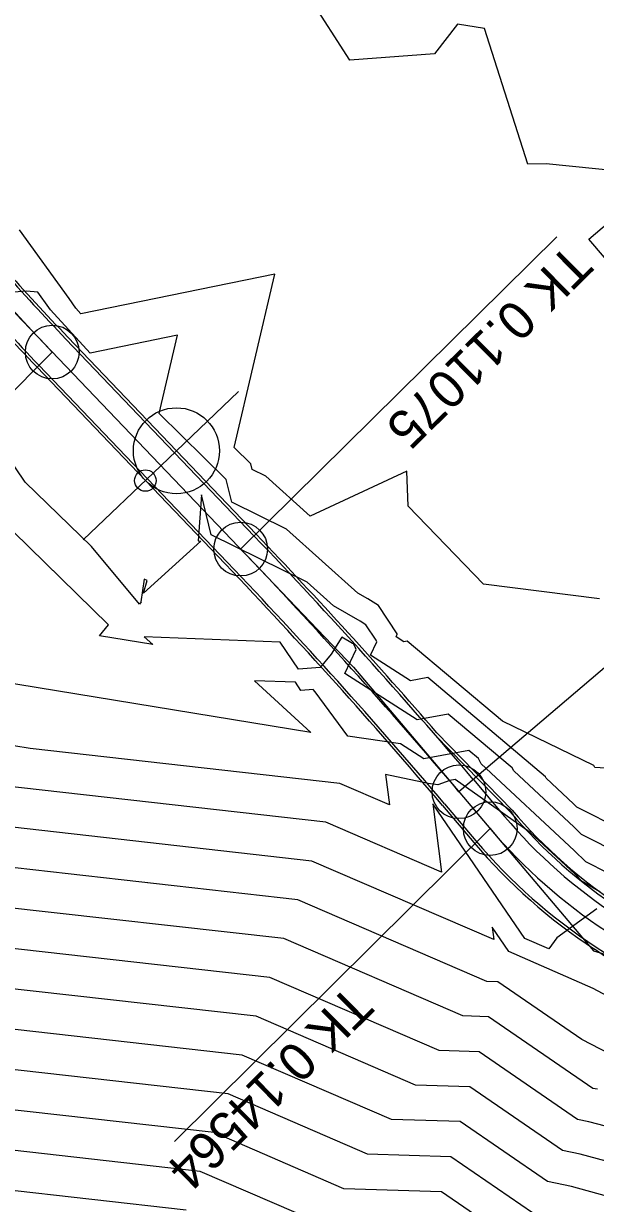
# Model space of a CAD drawing. Extents: x -549394 to -546608, y -1037055 to -1033629.
# Drawn here: x -547053.3 to -547000.1, y -1035904.5 to -1035794.7 of the extents above; entities that cross this region are included whole.
import ezdxf

# ---------------------------------------------------------------- set-up
doc = ezdxf.new("R2010")
doc.units = 0
for name, color, linetype in [('hlavni_vrst', 7, 'Continuous'), ('norm_vrst', 7, 'Continuous'), ('POLYGONY_SITUACE_PO', 7, 'Continuous'), ('u_sirka_7m', 7, 'Continuous'), ('x_navrh_C31', 7, 'Continuous'), ('x_osa_C31', 7, 'Continuous'), ('x_popis_oblouky_C31', 7, 'Continuous'), ('x_popis_pricne_rezy_C31', 7, 'Continuous')]:
    doc.layers.add(name, color=color, linetype=linetype)

msp = doc.modelspace()

# ---------------------------------------------------------------- linework, layer by layer
at = {"layer": 'hlavni_vrst'}
for p, q in [((-547022.93, -1035798.11), (-547032.16, -1035783.69)), ((-547012.88, -1035794.76), (-547015.05, -1035797.51)), ((-547010.39, -1035795.15), (-547012.88, -1035794.76)), ((-547006.35, -1035807.78), (-547010.39, -1035795.15)), ((-547015.05, -1035797.51), (-547022.93, -1035798.11)), ((-547004.64, -1035807.74), (-547006.35, -1035807.78)), ((-546981.44, -1035810.13), (-547004.64, -1035807.74)), ((-547026.55, -1035860.67), (-547059.01, -1035855.36)), ((-547027.98, -1035856), (-547031.79, -1035855.85)), ((-547031.79, -1035855.85), (-547026.55, -1035860.67)), ((-547027.47, -1035856.76), (-547027.98, -1035856)), ((-547026.32, -1035856.66), (-547027.47, -1035856.76)), ((-547026.15, -1035856.88), (-547026.32, -1035856.66)), ((-547023.09, -1035861.02), (-547026.15, -1035856.88)), ((-547018.2, -1035861.72), (-547023.09, -1035861.02)), ((-547016.02, -1035863.11), (-547018.2, -1035861.72)), ((-547011.83, -1035862.34), (-547016.02, -1035863.11)), ((-547010.93, -1035863.1), (-547011.83, -1035862.34)), ((-547010.68, -1035863.58), (-547010.93, -1035863.1)), ((-547002.02, -1035871.66), (-547010.68, -1035863.58)), ((-547000.95, -1035872.71), (-547002.02, -1035871.66)), ((-546998.88, -1035873.76), (-547000.95, -1035872.71)), ((-547029.05, -1035879.86), (-547076.55, -1035874.51)), ((-547012.39, -1035887.05), (-547029.05, -1035879.86)), ((-547010, -1035887.13), (-547012.39, -1035887.05)), ((-547000.3, -1035893.79), (-547010, -1035887.13)), ((-547035.55, -1035897.91), (-547069.97, -1035894.04)), ((-546999.85, -1035893.88), (-547000.3, -1035893.79)), ((-547023.48, -1035903.13), (-547035.55, -1035897.91)), ((-547014.4, -1035903.41), (-547023.48, -1035903.13)), ((-547007.32, -1035908.26), (-547014.4, -1035903.41))]:
    msp.add_line(p, q, dxfattribs=at)
at = {"layer": 'norm_vrst'}
for p, q in [((-547049.05, -1035820.28), (-547053.67, -1035813.88)), ((-547029.89, -1035818), (-547047.95, -1035821.71)), ((-547033.69, -1035834.15), (-547029.89, -1035818)), ((-547053, -1035819.58), (-547058.28, -1035820.05)), ((-547051.96, -1035819.69), (-547053, -1035819.58)), ((-547050.92, -1035821.13), (-547051.96, -1035819.69)), ((-547048.43, -1035821.18), (-547049.05, -1035820.28)), ((-547050.78, -1035821.33), (-547050.92, -1035821.13)), ((-547047.1, -1035825.36), (-547050.78, -1035821.33)), ((-547047.95, -1035821.71), (-547048.43, -1035821.18)), ((-547038.96, -1035823.69), (-547047.1, -1035825.36)), ((-547040.67, -1035830.97), (-547038.96, -1035823.69)), ((-547053.13, -1035837.36), (-547061.62, -1035824.89)), ((-547034.43, -1035837.12), (-547040.67, -1035830.97)), ((-547032.14, -1035835.68), (-547033.69, -1035834.15)), ((-547032.01, -1035836.2), (-547032.14, -1035835.68)), ((-547030.74, -1035836.82), (-547032.01, -1035836.2)), ((-547026.61, -1035840.53), (-547030.74, -1035836.82)), ((-547017.6, -1035836.34), (-547026.61, -1035840.53)), ((-547017.49, -1035839.62), (-547017.6, -1035836.34)), ((-547046.97, -1035843.36), (-547053.13, -1035837.36)), ((-547033.91, -1035839.23), (-547034.43, -1035837.12)), ((-547045.37, -1035850.64), (-547057.84, -1035838.49)), ((-547036.73, -1035838.56), (-547037.02, -1035842.84)), ((-547036.73, -1035838.56), (-547036.73, -1035838.56)), ((-547036.73, -1035838.56), (-547036.73, -1035838.56)), ((-547036.73, -1035838.56), (-547036.73, -1035838.56)), ((-547035.81, -1035842.27), (-547036.73, -1035838.56)), ((-547036.73, -1035838.56), (-547036.73, -1035838.56)), ((-547028.82, -1035841.75), (-547033.91, -1035839.23)), ((-547010.48, -1035846.87), (-547017.49, -1035839.62)), ((-547026.9, -1035846.67), (-547035.81, -1035842.27)), ((-547022.17, -1035847.7), (-547028.82, -1035841.75)), ((-547042.5, -1035848.72), (-547046.97, -1035843.36)), ((-547036.78, -1035842.86), (-547042.12, -1035847.7)), ((-547037.02, -1035842.84), (-547036.78, -1035842.86)), ((-547042.05, -1035846.39), (-547042.36, -1035848.5)), ((-547042.12, -1035847.7), (-547041.78, -1035846.51)), ((-547041.78, -1035846.51), (-547042.05, -1035846.39)), ((-547024.43, -1035848.88), (-547026.9, -1035846.67)), ((-546999.67, -1035848.23), (-547010.48, -1035846.87)), ((-547021.24, -1035848.24), (-547022.17, -1035847.7)), ((-547042.35, -1035848.5), (-547042.5, -1035848.72)), ((-547042.36, -1035848.5), (-547042.35, -1035848.5)), ((-547021.95, -1035850.32), (-547024.43, -1035848.88)), ((-547020.25, -1035848.84), (-547021.24, -1035848.24)), ((-547018.51, -1035851.5), (-547020.25, -1035848.84)), ((-547046.22, -1035851.68), (-547045.37, -1035850.64)), ((-547021.42, -1035850.64), (-547021.95, -1035850.32)), ((-547020.48, -1035852.07), (-547021.42, -1035850.64)), ((-547041.27, -1035852.49), (-547046.22, -1035851.68)), ((-547029.41, -1035852.27), (-547042.07, -1035851.76)), ((-547042.07, -1035851.76), (-547041.27, -1035852.49)), ((-547027.71, -1035854.78), (-547029.41, -1035852.27)), ((-547023.65, -1035851.81), (-547024.65, -1035853.38)), ((-547022.66, -1035852.39), (-547023.65, -1035851.81)), ((-547021, -1035853.48), (-547020.41, -1035852.24)), ((-547020.41, -1035852.24), (-547020.48, -1035852.07)), ((-547018.61, -1035851.77), (-547018.5, -1035851.53)), ((-547017.89, -1035852.23), (-547018.61, -1035851.77)), ((-547018.5, -1035851.53), (-547018.51, -1035851.5)), ((-547017.58, -1035852.17), (-547017.89, -1035852.23)), ((-547008.72, -1035859.63), (-547017.58, -1035852.17)), ((-547024.65, -1035853.38), (-547025.67, -1035854.61)), ((-547023.39, -1035855.18), (-547022.33, -1035852.94)), ((-547022.58, -1035852.43), (-547022.66, -1035852.39)), ((-547022.45, -1035852.64), (-547022.58, -1035852.43)), ((-547022.33, -1035852.94), (-547022.45, -1035852.64)), ((-547017.27, -1035855.86), (-547021, -1035853.48)), ((-547025.67, -1035854.61), (-547027.71, -1035854.78)), ((-547016.64, -1035859.48), (-547023.39, -1035855.18)), ((-547015.67, -1035855.56), (-547017.27, -1035855.86)), ((-547004.7, -1035864.79), (-547015.67, -1035855.56)), ((-547013.75, -1035858.95), (-547016.64, -1035859.48)), ((-547007.82, -1035863.95), (-547013.75, -1035858.95)), ((-547052.67, -1035862.17), (-547071.8, -1035859.05)), ((-547000.2, -1035863.74), (-547008.72, -1035859.63)), ((-547023.85, -1035865.42), (-547052.67, -1035862.17)), ((-547025.15, -1035869.03), (-547080.5, -1035862.79)), ((-547007.66, -1035864.25), (-547007.82, -1035863.95)), ((-547002.05, -1035869.48), (-547007.66, -1035864.25)), ((-547000.12, -1035863.94), (-547000.2, -1035863.74)), ((-546986.77, -1035864.7), (-547000.12, -1035863.94)), ((-547019.23, -1035867.41), (-547023.85, -1035865.42)), ((-547015.62, -1035865.42), (-547019.59, -1035864.57)), ((-547019.59, -1035864.57), (-547019.23, -1035867.41)), ((-547014.73, -1035865.55), (-547015.62, -1035865.42)), ((-547013.6, -1035865.14), (-547014.73, -1035865.55)), ((-547013.12, -1035865.05), (-547013.6, -1035865.14)), ((-547006.14, -1035869.97), (-547013.12, -1035865.05)), ((-547004.63, -1035864.93), (-547004.7, -1035864.79)), ((-547002.09, -1035867.3), (-547004.63, -1035864.93)), ((-547026.45, -1035872.64), (-547079.18, -1035866.7)), ((-547015.18, -1035867.31), (-547014.37, -1035873.68)), ((-547006.62, -1035879.84), (-547015.18, -1035867.31)), ((-547001.78, -1035867.61), (-547002.09, -1035867.3)), ((-546991.23, -1035872.96), (-547001.78, -1035867.61)), ((-547014.37, -1035873.68), (-547025.15, -1035869.03)), ((-547001.36, -1035870.16), (-547002.05, -1035869.48)), ((-547027.75, -1035876.25), (-547077.87, -1035870.6)), ((-547001.98, -1035873.84), (-547006.14, -1035869.97)), ((-546995.05, -1035873.36), (-547001.36, -1035870.16)), ((-547009.51, -1035879.95), (-547026.45, -1035872.64)), ((-547001.28, -1035874.54), (-547001.98, -1035873.84)), ((-546999.65, -1035875.5), (-547001.28, -1035874.54)), ((-547010.17, -1035883.84), (-547027.75, -1035876.25)), ((-546999.92, -1035877.08), (-547003.66, -1035879.79)), ((-547030.35, -1035883.47), (-547075.24, -1035878.41)), ((-547009.66, -1035878.8), (-547009.51, -1035879.95)), ((-547008.11, -1035881.06), (-547009.66, -1035878.8)), ((-547003.66, -1035879.79), (-547004.38, -1035880.82)), ((-547004.38, -1035880.82), (-547006.62, -1035879.84)), ((-547000.28, -1035884.51), (-547008.11, -1035881.06)), ((-547031.65, -1035887.08), (-547073.92, -1035882.32)), ((-547014.61, -1035890.27), (-547030.35, -1035883.47)), ((-547009.13, -1035883.87), (-547010.17, -1035883.84)), ((-547001.32, -1035889.23), (-547009.13, -1035883.87)), ((-546996.77, -1035886.37), (-547000.28, -1035884.51)), ((-547032.95, -1035890.69), (-547072.6, -1035886.22)), ((-547016.82, -1035893.48), (-547031.65, -1035887.08)), ((-546998.76, -1035890.59), (-547001.32, -1035889.23)), ((-547034.25, -1035894.3), (-547071.29, -1035890.13)), ((-547019.04, -1035896.7), (-547032.95, -1035890.69)), ((-547010.88, -1035890.38), (-547014.61, -1035890.27)), ((-547001.71, -1035896.68), (-547010.88, -1035890.38)), ((-547011.76, -1035893.64), (-547016.82, -1035893.48)), ((-547003.11, -1035899.58), (-547011.76, -1035893.64)), ((-547021.26, -1035899.91), (-547034.25, -1035894.3)), ((-547012.64, -1035896.89), (-547019.04, -1035896.7)), ((-547004.51, -1035902.47), (-547012.64, -1035896.89)), ((-547000.66, -1035896.9), (-547001.71, -1035896.68)), ((-546999.13, -1035897.31), (-547000.66, -1035896.9)), ((-547036.85, -1035901.52), (-547068.66, -1035897.94)), ((-547001.48, -1035899.92), (-547003.11, -1035899.58)), ((-547013.52, -1035900.15), (-547021.26, -1035899.91)), ((-547005.92, -1035905.37), (-547013.52, -1035900.15)), ((-546999.07, -1035900.56), (-547001.48, -1035899.92)), ((-547025.69, -1035906.34), (-547036.85, -1035901.52)), ((-547038.15, -1035905.14), (-547067.34, -1035901.85)), ((-547002.29, -1035902.93), (-547004.51, -1035902.47)), ((-546999.02, -1035903.82), (-547002.29, -1035902.93))]:
    msp.add_line(p, q, dxfattribs=at)
at = {"layer": 'POLYGONY_SITUACE_PO'}
for centre in [(-547050.62, -1035825.26), (-547033.08, -1035843.6), (-547012.76, -1035866.19), (-547009.85, -1035869.62)]:
    msp.add_circle(centre, 2.5, dxfattribs=at)
at = {"layer": 'u_sirka_7m'}
for centre, radius in [((-547039.06, -1035834.45), 4), ((-547041.95, -1035837.22), 1)]:
    msp.add_circle(centre, radius, dxfattribs=at)
at = {"layer": 'x_navrh_C31'}
for p, q in [((-547049.35, -1035824.06), (-547031.82, -1035842.39)), ((-547051.88, -1035826.47), (-547034.35, -1035844.81)), ((-547008, -1035868.06), (-547015, -1035860.88)), ((-547007.82, -1035867.89), (-547014.81, -1035860.71)), ((-547011.42, -1035865.06), (-547008.52, -1035868.49)), ((-547014.09, -1035867.32), (-547011.19, -1035870.75)), ((-546989.45, -1035888.32), (-547000.14, -1035880.85))]:
    msp.add_line(p, q, dxfattribs=at)
for points in [[(-547049.17, -1035823.88), (-547031.64, -1035842.22)], [(-547052.06, -1035826.65), (-547034.53, -1035844.98)], [(-547014.29, -1035867.48), (-547011.38, -1035870.91)]]:
    msp.add_lwpolyline(points, dxfattribs=at)
for centre, radius, start, end in [((-546869.94, -1035652.47), 248.25, 219.6688, 223.7225), ((-546869.94, -1035652.47), 248, 219.6688, 223.7225), ((-546869.94, -1035652.47), 252, 219.6688, 223.7225), ((-546869.94, -1035652.47), 251.75, 219.6688, 223.7225), ((-547394.43, -1036189.18), 501.75, 40.24, 43.7225), ((-547394.43, -1036189.18), 502, 40.8688, 43.7225), ((-547394.43, -1036189.18), 498, 40.24, 43.7225), ((-547394.43, -1036189.18), 498.25, 40.24, 43.7225), ((-546971.68, -1035837.32), 48.25, 220.24, 253.4173), ((-546971.68, -1035837.32), 47.58, 220.24, 253.4173), ((-546971.68, -1035837.32), 47.33, 220.2295, 253.4274), ((-546971.68, -1035837.32), 52, 220.24, 236.8244), ((-546971.68, -1035837.32), 51.75, 220.24, 253.4173)]:
    msp.add_arc(centre, radius, start, end, dxfattribs=at)
at = {"layer": 'x_osa_C31'}
for points in [[(-547102.02, -1035757.3), (-547080.39, -1035790.35), (-547080.39, -1035790.35), (-547056.73, -1035818.87), (-547022.58, -1035854.58), (-547022.58, -1035854.58), (-547000.23, -1035880.99)], [(-547000.23, -1035880.99), (-546956.23, -1035894.09)]]:
    msp.add_lwpolyline(points, dxfattribs=at)
for centre, radius, start, end in [((-546869.94, -1035652.47), 250, 219.6688, 223.7225), ((-547394.43, -1036189.18), 500, 40.24, 43.7225), ((-546971.68, -1035837.32), 50, 220.24, 253.4173)]:
    msp.add_arc(centre, radius, start, end, dxfattribs=at)
at = {"layer": 'x_popis_oblouky_C31'}
msp.add_lwpolyline([(-546996.12, -1035810.87), (-546976.62, -1035833.67), (-546981.18, -1035837.57), (-547000.68, -1035814.77)], close=True, dxfattribs=at)
for points in [[(-547003.64, -1035814.54), (-547033.08, -1035843.6)], [(-547050.62, -1035825.26), (-547079.8, -1035854.6)], [(-546981.26, -1035839.36), (-547012.76, -1035866.19)], [(-547009.85, -1035869.62), (-547039.24, -1035898.74)]]:
    msp.add_lwpolyline(points, dxfattribs=at)
at = {"layer": 'x_popis_pricne_rezy_C31'}
msp.add_lwpolyline([(-547033.28, -1035828.92), (-547040.51, -1035835.84), (-547047.73, -1035842.75)], dxfattribs=at)

# ---------------------------------------------------------------- texts
at = {"layer": 'x_popis_oblouky_C31'}
for s, rotation, p in [('TK 0.11075', 224.6217, (-547002.55, -1035815.04)), ('TK 0.14564', 224.7408, (-547022.97, -1035884.02))]:
    msp.add_text(s, height=3.5, rotation=rotation, dxfattribs=at).set_placement(p)

doc.saveas('drawing.dxf')
